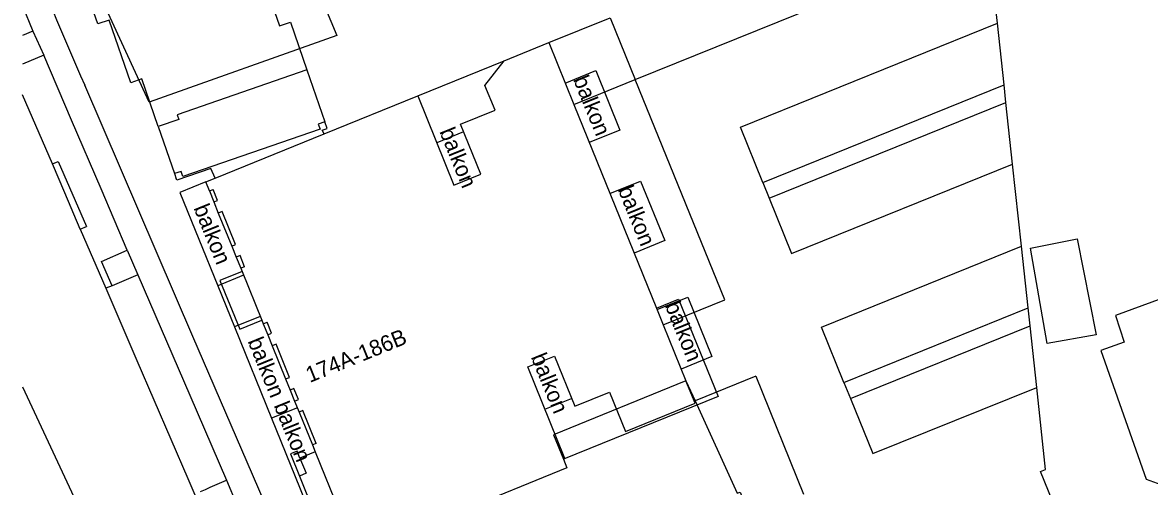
# Model space of a CAD drawing. Extents: x 194485 to 197793, y 468269 to 470822.
# Drawn here: x 194485.4 to 194570.5, y 469890.9 to 469925.9 of the extents above; entities that cross this region are included whole.
import ezdxf

# ---------------------------------------------------------------- set-up
doc = ezdxf.new("R2010")
doc.units = 0
for name, color, linetype in [('BAG plantopografie panden grensvlak verbouwing pand', 7, 'Continuous'), ('BAG plantopografie panden lijnelement overig', 7, 'Continuous'), ('BAG plantopografie panden tekst opmerking', 7, 'Continuous'), ('BGT begrenzing pand op maaiveld onder overbouw', 7, 'Continuous'), ('BGT begrenzing pand te verbouwen', 7, 'Continuous'), ('BGT grensvlak gebouwinstallatie plus 1', 7, 'Continuous'), ('BGT grensvlak onbegroeid terreindeel', 7, 'Continuous'), ('BGT grensvlak pand deel overbouw', 7, 'Continuous'), ('BGT grensvlak pand min 1', 7, 'Continuous'), ('BGT grensvlak pand op maaiveld', 7, 'Continuous'), ('BGT grensvlak pand op maaiveld LR', 7, 'Continuous'), ('BGT grensvlak wegdeel', 7, 'Continuous'), ('BGT tekst huisnummerreeks', 7, 'Continuous')]:
    doc.layers.add(name, color=color, linetype=linetype)

msp = doc.modelspace()

# ---------------------------------------------------------------- linework, layer by layer
at = {"layer": 'BAG plantopografie panden grensvlak verbouwing pand'}
for p, q in [((194523.567, 469899.937), (194525.587, 469900.757)), ((194525.587, 469900.757), (194527.122, 469896.977)), ((194526.377, 469893.016), (194523.567, 469899.937)), ((194526.266, 469892.971), (194526.377, 469893.016))]:
    msp.add_line(p, q, dxfattribs=at)
for points in [[(194515.255, 469920.404), (194517.994, 469913.659), (194520.014, 469914.479), (194518.479, 469918.259), (194521.096, 469919.322), (194520.336, 469921.194), (194521.786, 469923.056)], [(194527.122, 469896.977), (194529.739, 469898.04), (194530.943, 469895.075), (194536.201, 469897.211), (194535.52, 469898.888)]]:
    msp.add_lwpolyline(points, dxfattribs=at)
at = {"layer": 'BAG plantopografie panden lijnelement overig'}
for p, q in [((194526.392, 469921.365), (194528.708, 469922.305)), ((194528.708, 469922.305), (194530.533, 469917.812)), ((194518.716, 469917.675), (194516.696, 469916.855)), ((194530.533, 469917.812), (194528.217, 469916.871)), ((194499.245, 469913.902), (194497.299, 469913.112)), ((194529.778, 469913.026), (194532.094, 469913.967)), ((194532.094, 469913.967), (194533.919, 469909.473)), ((194497.299, 469913.112), (194500.16, 469906.067)), ((194533.919, 469909.473), (194531.603, 469908.533)), ((194502.106, 469906.857), (194500.16, 469906.067)), ((194500.16, 469906.067), (194501.421, 469902.963)), ((194533.334, 469904.271), (194535.65, 469905.211)), ((194535.65, 469905.211), (194537.475, 469900.718)), ((194503.366, 469903.753), (194501.421, 469902.963)), ((194501.421, 469902.963), (194504.224, 469896.061)), ((194537.475, 469900.718), (194535.159, 469899.777)), ((194524.865, 469896.741), (194526.885, 469897.561)), ((194506.169, 469896.851), (194504.224, 469896.061)), ((194504.224, 469896.061), (194508.241, 469886.169))]:
    msp.add_line(p, q, dxfattribs=at)
at = {"layer": 'BGT begrenzing pand op maaiveld onder overbouw'}
for p, q in [((194506.894, 469922.366), (194497.09, 469918.978)), ((194497.214, 469918.62), (194495.667, 469918.085)), ((194497.09, 469918.978), (194497.214, 469918.62)), ((194499.52, 469913.225), (194499.808, 469913.342)), ((194500.147, 469912.509), (194499.808, 469913.342)), ((194499.858, 469912.392), (194500.147, 469912.509)), ((194500.485, 469911.675), (194500.197, 469911.558)), ((194501.501, 469909.173), (194500.485, 469911.675)), ((194501.213, 469909.056), (194501.501, 469909.173)), ((194501.84, 469908.339), (194501.551, 469908.222)), ((194502.178, 469907.505), (194501.84, 469908.339)), ((194502.178, 469907.505), (194501.89, 469907.388)), ((194503.591, 469903.201), (194503.879, 469903.317)), ((194504.217, 469902.484), (194503.879, 469903.317)), ((194503.929, 469902.367), (194504.217, 469902.484)), ((194504.556, 469901.65), (194504.268, 469901.533)), ((194505.571, 469899.148), (194504.556, 469901.65)), ((194505.284, 469899.031), (194505.571, 469899.148)), ((194505.91, 469898.314), (194505.623, 469898.197)), ((194506.248, 469897.48), (194505.91, 469898.314)), ((194505.961, 469897.364), (194506.248, 469897.48)), ((194506.587, 469896.646), (194506.3, 469896.53)), ((194507.595, 469894.163), (194506.587, 469896.646)), ((194507.595, 469894.163), (194507.308, 469894.047)), ((194506.364, 469893.064), (194506.832, 469891.91)), ((194507.517, 469893.532), (194510.147, 469887.056)), ((194506.832, 469891.91), (194506.318, 469891.702))]:
    msp.add_line(p, q, dxfattribs=at)
for points in [[(194508.248, 469918.44), (194507.747, 469918.267), (194507.881, 469917.879), (194497.527, 469914.316)], [(194497.527, 469914.316), (194497.393, 469914.703), (194496.892, 469914.53)]]:
    msp.add_lwpolyline(points, dxfattribs=at)
at = {"layer": 'BGT begrenzing pand te verbouwen'}
for p, q in [((194515.255, 469920.404), (194521.786, 469923.056)), ((194535.52, 469898.888), (194525.514, 469894.824)), ((194525.514, 469894.824), (194526.266, 469892.971))]:
    msp.add_line(p, q, dxfattribs=at)
at = {"layer": 'BGT grensvlak gebouwinstallatie plus 1'}
for p, q in [((194501.991, 469907.139), (194500.324, 469906.462)), ((194500.324, 469906.462), (194501.813, 469902.795)), ((194533.291, 469904.376), (194534.959, 469905.054)), ((194534.959, 469905.054), (194537.94, 469897.712)), ((194501.813, 469902.795), (194503.481, 469903.472)), ((194537.94, 469897.712), (194526.266, 469892.971))]:
    msp.add_line(p, q, dxfattribs=at)
at = {"layer": 'BGT grensvlak onbegroeid terreindeel'}
for p, q in [((194525.15, 469924.422), (194529.793, 469926.3)), ((194559.687, 469919.897), (194559.542, 469921.241)), ((194561.505, 469903.05), (194561.36, 469904.394))]:
    msp.add_line(p, q, dxfattribs=at)
at = {"layer": 'BGT grensvlak pand deel overbouw'}
for p, q in [((194506.894, 469922.366), (194508.248, 469918.44)), ((194495.667, 469918.085), (194496.892, 469914.53)), ((194499.52, 469913.225), (194499.858, 469912.392)), ((194500.197, 469911.558), (194501.213, 469909.056)), ((194501.551, 469908.222), (194501.89, 469907.388)), ((194503.591, 469903.201), (194503.929, 469902.367)), ((194504.268, 469901.533), (194505.284, 469899.031)), ((194505.623, 469898.197), (194505.961, 469897.364)), ((194506.3, 469896.53), (194507.308, 469894.047)), ((194507.517, 469893.532), (194506.364, 469893.064)), ((194506.318, 469891.702), (194508.011, 469887.532))]:
    msp.add_line(p, q, dxfattribs=at)
at = {"layer": 'BGT grensvlak pand min 1'}
for points in [[(194485.411, 469951.236), (194499.221, 469955.978), (194502.735, 469946.345), (194498.434, 469944.891), (194499.888, 469940.711), (194501.16, 469941.169), (194502.69, 469940.442), (194509.158, 469924.958)], [(194509.158, 469924.958), (194494.98, 469919.93), (194485.411, 469940.712)]]:
    msp.add_lwpolyline(points, dxfattribs=at)
at = {"layer": 'BGT grensvlak pand op maaiveld'}
for p, q in [((194521.786, 469923.056), (194525.15, 469924.422)), ((194525.15, 469924.422), (194527.047, 469919.751)), ((194508.188, 469917.534), (194515.255, 469920.404)), ((194527.047, 469919.751), (194533.291, 469904.376)), ((194496.892, 469914.53), (194497.025, 469914.143)), ((194499.245, 469913.902), (194499.961, 469914.193)), ((194499.52, 469913.225), (194499.245, 469913.902)), ((194499.858, 469912.392), (194500.197, 469911.558)), ((194501.213, 469909.056), (194501.551, 469908.222)), ((194501.89, 469907.388), (194501.991, 469907.139)), ((194501.991, 469907.139), (194503.481, 469903.472)), ((194533.291, 469904.376), (194533.801, 469903.121)), ((194503.481, 469903.472), (194503.591, 469903.201)), ((194533.801, 469903.121), (194535.52, 469898.888)), ((194503.929, 469902.367), (194504.268, 469901.533)), ((194505.284, 469899.031), (194505.623, 469898.197)), ((194505.961, 469897.364), (194506.3, 469896.53)), ((194507.308, 469894.047), (194507.517, 469893.532)), ((194506.155, 469893.578), (194505.641, 469893.369)), ((194505.641, 469893.369), (194506.318, 469891.702)), ((194506.364, 469893.064), (194506.155, 469893.578)), ((194526.266, 469892.971), (194526.53, 469892.322)), ((194526.53, 469892.322), (194510.631, 469885.866))]:
    msp.add_line(p, q, dxfattribs=at)
for points in [[(194495.604, 469954.82), (194499.375, 469956.113), (194502.77, 469946.415), (194496.361, 469944.141), (194497.715, 469940.336), (194498.689, 469940.672), (194501.297, 469933.048), (194502.138, 469933.338), (194504.809, 469925.682), (194505.651, 469925.972), (194506.894, 469922.366)], [(194495.667, 469918.085), (194494.425, 469921.687), (194493.585, 469921.395), (194491.951, 469926.128), (194491.096, 469925.844), (194487.379, 469936.391), (194486.547, 469936.105), (194485.411, 469939.285)], [(194508.188, 469917.534), (194508.052, 469917.811), (194508.421, 469917.938), (194508.248, 469918.44)], [(194499.961, 469914.193), (194499.636, 469914.915), (194497.065, 469914.029), (194497.025, 469914.143)], [(194561.536, 469908.915), (194565.063, 469909.602), (194566.496, 469902.359), (194562.803, 469901.717), (194561.536, 469908.915)], [(194575.105, 469904.1), (194572.68, 469903.24), (194571.941, 469905.285), (194567.951, 469903.833), (194568.627, 469901.801), (194566.844, 469901.189), (194570.272, 469891.475), (194571.387, 469891.07), (194573.781, 469891.924), (194574.498, 469893.153), (194578.502, 469894.527)]]:
    msp.add_lwpolyline(points, dxfattribs=at)
at = {"layer": 'BGT grensvlak pand op maaiveld LR'}
msp.add_line((194499.961, 469914.193), (194508.188, 469917.534), dxfattribs=at)
at = {"layer": 'BGT grensvlak wegdeel'}
for p, q in [((194531.691, 469921.628), (194558.337, 469932.403)), ((194559.04, 469925.892), (194558.337, 469932.403)), ((194485.411, 469927.204), (194486.185, 469925.298)), ((194529.793, 469926.3), (194531.691, 469921.628)), ((194486.185, 469925.298), (194485.411, 469924.967)), ((194486.185, 469925.298), (194487.014, 469923.468)), ((194559.542, 469921.241), (194559.04, 469925.892)), ((194487.014, 469923.468), (194485.411, 469922.784)), ((194527.047, 469919.751), (194531.691, 469921.628)), ((194541.318, 469913.871), (194559.542, 469921.241)), ((194487.677, 469915.261), (194485.411, 469920.488)), ((194541.807, 469912.667), (194559.687, 469919.897)), ((194560.189, 469915.246), (194559.687, 469919.897)), ((194487.677, 469915.261), (194488.114, 469915.437)), ((194560.858, 469909.045), (194560.189, 469915.246)), ((194541.318, 469913.871), (194541.807, 469912.667)), ((194489.775, 469910.343), (194490.231, 469910.528)), ((194489.775, 469910.343), (194491.705, 469905.875)), ((194561.36, 469904.394), (194560.858, 469909.045)), ((194491.385, 469907.897), (194493.316, 469908.749)), ((194493.316, 469908.749), (194494.124, 469906.895)), ((194492.17, 469906.071), (194491.385, 469907.897)), ((194494.124, 469906.895), (194492.17, 469906.071)), ((194492.17, 469906.071), (194491.705, 469905.875)), ((194547.453, 469898.77), (194561.36, 469904.394)), ((194547.942, 469897.565), (194561.505, 469903.05)), ((194562.007, 469898.399), (194561.505, 469903.05)), ((194535.52, 469898.888), (194536.206, 469897.382)), ((194540.785, 469899.242), (194536.206, 469897.382)), ((194540.785, 469899.242), (194544.401, 469890.341)), ((194547.453, 469898.77), (194547.942, 469897.565)), ((194485.411, 469898.45), (194494.108, 469879.84)), ((194563.232, 469889.763), (194562.308, 469892.049)), ((194500.808, 469891.394), (194501.608, 469889.53))]:
    msp.add_line(p, q, dxfattribs=at)
for points in [[(194541.318, 469913.871), (194539.625, 469918.041), (194559.04, 469925.892)], [(194493.316, 469908.749), (194491.339, 469913.376), (194489.108, 469918.564), (194487.014, 469923.468)], [(194510.654, 469873.605), (194498.28, 469902.243), (194490.105, 469921.206)], [(194533.801, 469903.121), (194538.443, 469905.006), (194531.691, 469921.628)], [(194489.775, 469910.343), (194488.598, 469913.085), (194487.677, 469915.261)], [(194488.114, 469915.437), (194489.382, 469912.504), (194490.231, 469910.528)], [(194541.807, 469912.667), (194543.501, 469908.498), (194560.189, 469915.246)], [(194547.453, 469898.77), (194545.759, 469902.939), (194560.858, 469909.045)], [(194494.124, 469906.895), (194498.035, 469897.81), (194500.808, 469891.394)], [(194491.705, 469905.875), (194494.053, 469900.437), (194497.896, 469891.525), (194501.426, 469883.317), (194503.123, 469879.66), (194504.705, 469876.155)], [(194547.942, 469897.565), (194549.636, 469893.396), (194562.007, 469898.399)], [(194562.308, 469892.049), (194562.676, 469892.198), (194562.007, 469898.399)], [(194536.206, 469897.382), (194539.38, 469890.41), (194539.62, 469890.49), (194540.35, 469888.696)], [(194498.853, 469890.528), (194499.225, 469890.693), (194499.59, 469890.854), (194500.808, 469891.394)]]:
    msp.add_lwpolyline(points, dxfattribs=at)
msp.add_arc((194740.286, 470031.295), 273.332, 201.17613, 203.75136, dxfattribs=at)

# ---------------------------------------------------------------- texts
at = {"layer": 'BAG plantopografie panden tekst opmerking'}
for p in [(194526.979, 469921.648), (194516.876, 469917.716), (194530.356, 469913.333), (194498.315, 469911.94), (194533.904, 469904.596), (194502.397, 469901.89), (194523.79, 469900.691), (194504.368, 469897.034)]:
    msp.add_text('balkon', height=1.2, rotation=292.10464, dxfattribs=at).set_placement(p)
at = {"layer": 'BGT tekst huisnummerreeks'}
msp.add_text('174A-186B', height=1.2, rotation=22.1, dxfattribs=at).set_placement((194507.103, 469898.728))

doc.saveas('drawing.dxf')
